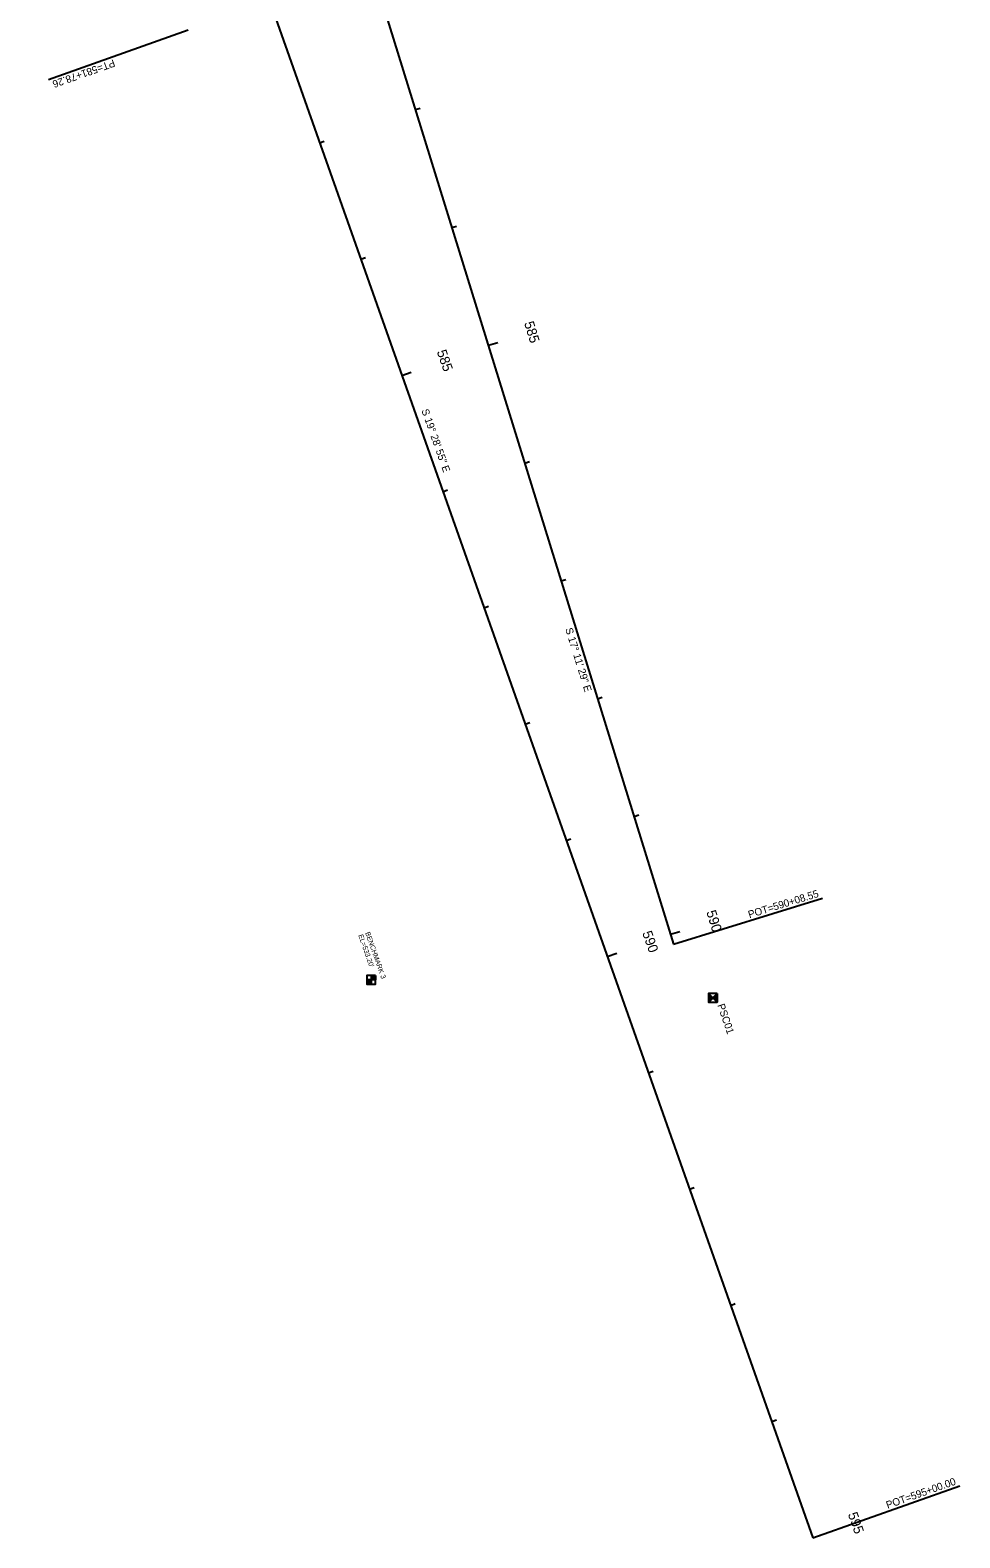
# Model space of a CAD drawing. Extents: x 2004390 to 2008791, y 1133870 to 1140084.
# Drawn here: x 2006440 to 2007194, y 1133870 to 1135092 of the extents above; entities that cross this region are included whole.
import ezdxf

# ---------------------------------------------------------------- set-up
doc = ezdxf.new("R2010")
doc.units = 0
for name, color, linetype in [('RD_HC_Cl', 7, 'Continuous'), ('RD_HC_Data', 7, 'Continuous'), ('RD_HC_Data_Tic', 7, 'Continuous'), ('RD_HC_Survey', 7, 'Continuous'), ('RD_HC_Survey_txCode', 7, 'Continuous'), ('RD_HC_TX_Sta50', 7, 'Continuous')]:
    doc.layers.add(name, color=color, linetype=linetype)

msp = doc.modelspace()

# ---------------------------------------------------------------- linework, layer by layer
at = {"layer": 'RD_HC_Cl'}
for p, q in [((2005036.1, 1139633.5), (2007075.2, 1133869.8)), ((2006488, 1135883.7), (2006962.2, 1134351.1))]:
    msp.add_line(p, q, dxfattribs=at)
at = {"layer": 'RD_HC_Data'}
for p, q in [((2006568.4, 1135092.5), (2006454.9, 1135052.3)), ((2006962.2, 1134351.1), (2007083, 1134388.5)), ((2007075.2, 1133869.8), (2007194.4, 1133912))]:
    msp.add_line(p, q, dxfattribs=at)
at = {"layer": 'RD_HC_Data_Tic'}
for p, q in [((2006752.7, 1135028), (2006756.6, 1135029.2)), ((2006675, 1135001.1), (2006678.7, 1135002.4)), ((2006782.3, 1134932.5), (2006786.1, 1134933.6)), ((2006708.3, 1134906.8), (2006712.1, 1134908.1)), ((2006811.9, 1134836.9), (2006819.5, 1134839.3)), ((2006741.7, 1134812.5), (2006749.2, 1134815.2)), ((2006841.4, 1134741.4), (2006845.2, 1134742.6)), ((2006775, 1134718.2), (2006778.8, 1134719.6)), ((2006871, 1134645.9), (2006874.8, 1134647)), ((2006808.4, 1134624), (2006812.1, 1134625.3)), ((2006900.5, 1134550.3), (2006904.3, 1134551.5)), ((2006841.7, 1134529.7), (2006845.5, 1134531)), ((2006930.1, 1134454.8), (2006933.9, 1134456)), ((2006875.1, 1134435.4), (2006878.8, 1134436.7)), ((2006959.6, 1134359.3), (2006967.3, 1134361.6)), ((2006908.4, 1134341.1), (2006916, 1134343.8)), ((2006941.8, 1134246.9), (2006945.5, 1134248.2)), ((2006975.1, 1134152.6), (2006978.9, 1134153.9)), ((2007008.5, 1134058.3), (2007012.2, 1134059.7)), ((2007041.8, 1133964), (2007045.6, 1133965.4)), ((2007075.2, 1133869.8), (2007082.7, 1133872.4))]:
    msp.add_line(p, q, dxfattribs=at)
at = {"layer": 'RD_HC_Survey'}
for p, q in [((2006720.3, 1134322.3), (2006713.3, 1134322.3)), ((2006713.3, 1134322.3), (2006713.3, 1134318.8)), ((2006713.3, 1134322.3), (2006713.3, 1134318.8)), ((2006713.4, 1134322.3), (2006713.4, 1134318.8)), ((2006713.4, 1134322.3), (2006713.4, 1134318.8)), ((2006713.5, 1134322.3), (2006713.5, 1134318.8)), ((2006713.5, 1134322.3), (2006713.5, 1134318.8)), ((2006713.6, 1134322.3), (2006713.6, 1134318.8)), ((2006713.6, 1134322.3), (2006713.6, 1134318.8)), ((2006713.7, 1134322.3), (2006713.7, 1134318.8)), ((2006713.7, 1134322.3), (2006713.7, 1134318.8)), ((2006713.8, 1134322.3), (2006713.8, 1134318.8)), ((2006713.8, 1134322.3), (2006713.8, 1134318.8)), ((2006713.9, 1134322.3), (2006713.9, 1134318.8)), ((2006713.9, 1134322.3), (2006713.9, 1134318.8)), ((2006714, 1134322.3), (2006714, 1134318.8)), ((2006714, 1134322.3), (2006714, 1134318.8)), ((2006714.1, 1134322.3), (2006714.1, 1134318.8)), ((2006714.1, 1134322.3), (2006714.1, 1134318.8)), ((2006714.2, 1134322.3), (2006714.2, 1134318.8)), ((2006714.2, 1134322.3), (2006714.2, 1134318.8)), ((2006714.3, 1134322.3), (2006714.3, 1134318.8)), ((2006714.3, 1134322.3), (2006714.3, 1134318.8)), ((2006714.4, 1134322.3), (2006714.4, 1134318.8)), ((2006714.4, 1134322.3), (2006714.4, 1134318.8)), ((2006714.5, 1134322.3), (2006714.5, 1134318.8)), ((2006714.5, 1134322.3), (2006714.5, 1134318.8)), ((2006714.6, 1134322.3), (2006714.6, 1134318.8)), ((2006714.6, 1134322.3), (2006714.6, 1134318.8)), ((2006714.7, 1134322.3), (2006714.7, 1134318.8)), ((2006714.7, 1134322.3), (2006714.7, 1134318.8)), ((2006714.8, 1134322.3), (2006714.8, 1134318.8)), ((2006714.8, 1134322.3), (2006714.8, 1134318.8)), ((2006714.9, 1134322.3), (2006714.9, 1134318.8)), ((2006714.9, 1134322.3), (2006714.9, 1134318.8)), ((2006715, 1134322.3), (2006715, 1134318.8)), ((2006715, 1134322.3), (2006715, 1134318.8)), ((2006715.1, 1134322.3), (2006715.1, 1134318.8)), ((2006715.1, 1134322.3), (2006715.1, 1134318.8)), ((2006715.2, 1134322.3), (2006715.2, 1134318.8)), ((2006715.2, 1134322.3), (2006715.2, 1134318.8)), ((2006715.3, 1134322.3), (2006715.3, 1134318.8)), ((2006715.3, 1134322.3), (2006715.3, 1134318.8)), ((2006715.4, 1134322.3), (2006715.4, 1134318.8)), ((2006715.4, 1134322.3), (2006715.4, 1134318.8)), ((2006715.5, 1134322.3), (2006715.5, 1134318.8)), ((2006715.5, 1134322.3), (2006715.5, 1134318.8)), ((2006715.6, 1134322.3), (2006715.6, 1134318.8)), ((2006715.6, 1134322.3), (2006715.6, 1134318.8)), ((2006715.7, 1134322.3), (2006715.7, 1134318.8)), ((2006715.7, 1134322.3), (2006715.7, 1134318.8)), ((2006715.8, 1134322.3), (2006715.8, 1134318.8)), ((2006715.8, 1134322.3), (2006715.8, 1134318.8)), ((2006715.9, 1134322.3), (2006715.9, 1134318.8)), ((2006715.9, 1134322.3), (2006715.9, 1134318.8)), ((2006716, 1134322.3), (2006716, 1134318.8)), ((2006716, 1134322.3), (2006716, 1134318.8)), ((2006716.1, 1134322.3), (2006716.1, 1134318.8)), ((2006716.1, 1134322.3), (2006716.1, 1134318.8)), ((2006716.2, 1134322.3), (2006716.2, 1134318.8)), ((2006716.2, 1134322.3), (2006716.2, 1134318.8)), ((2006716.3, 1134322.3), (2006716.3, 1134318.8)), ((2006716.3, 1134322.3), (2006716.3, 1134318.8)), ((2006716.4, 1134322.3), (2006716.4, 1134318.8)), ((2006716.4, 1134322.3), (2006716.4, 1134318.8)), ((2006716.5, 1134322.3), (2006716.5, 1134318.8)), ((2006716.5, 1134322.3), (2006716.5, 1134318.8)), ((2006716.6, 1134322.3), (2006716.6, 1134318.8)), ((2006716.6, 1134322.3), (2006716.6, 1134318.8)), ((2006716.7, 1134322.3), (2006716.7, 1134318.8)), ((2006716.7, 1134322.3), (2006716.7, 1134318.8)), ((2006716.8, 1134325.8), (2006716.8, 1134318.8)), ((2006716.8, 1134325.8), (2006716.8, 1134322.3)), ((2006716.8, 1134322.3), (2006716.8, 1134318.8)), ((2006716.9, 1134325.8), (2006716.9, 1134322.3)), ((2006716.9, 1134325.8), (2006716.9, 1134322.3)), ((2006717, 1134325.8), (2006717, 1134322.3)), ((2006717, 1134325.8), (2006717, 1134322.3)), ((2006717.1, 1134325.8), (2006717.1, 1134322.3)), ((2006717.1, 1134325.8), (2006717.1, 1134322.3)), ((2006717.2, 1134325.8), (2006717.2, 1134322.3)), ((2006717.2, 1134325.8), (2006717.2, 1134322.3)), ((2006717.3, 1134325.8), (2006717.3, 1134322.3)), ((2006717.3, 1134325.8), (2006717.3, 1134322.3)), ((2006717.4, 1134325.8), (2006717.4, 1134322.3)), ((2006717.4, 1134325.8), (2006717.4, 1134322.3)), ((2006717.5, 1134325.8), (2006717.5, 1134322.3)), ((2006717.5, 1134325.8), (2006717.5, 1134322.3)), ((2006717.6, 1134325.8), (2006717.6, 1134322.3)), ((2006717.6, 1134325.8), (2006717.6, 1134322.3)), ((2006717.7, 1134325.8), (2006717.7, 1134322.3)), ((2006717.7, 1134325.8), (2006717.7, 1134322.3)), ((2006717.8, 1134325.8), (2006717.8, 1134322.3)), ((2006717.8, 1134325.8), (2006717.8, 1134322.3)), ((2006717.9, 1134325.8), (2006717.9, 1134322.3)), ((2006717.9, 1134325.8), (2006717.9, 1134322.3)), ((2006718, 1134325.8), (2006718, 1134322.3)), ((2006718, 1134325.8), (2006718, 1134322.3)), ((2006718.1, 1134325.8), (2006718.1, 1134322.3)), ((2006718.1, 1134325.8), (2006718.1, 1134322.3)), ((2006718.2, 1134325.8), (2006718.2, 1134322.3)), ((2006718.2, 1134325.8), (2006718.2, 1134322.3)), ((2006718.3, 1134325.8), (2006718.3, 1134322.3)), ((2006718.3, 1134325.8), (2006718.3, 1134322.3)), ((2006718.4, 1134325.8), (2006718.4, 1134322.3)), ((2006718.4, 1134325.8), (2006718.4, 1134322.3)), ((2006718.5, 1134325.8), (2006718.5, 1134322.3)), ((2006718.5, 1134325.8), (2006718.5, 1134322.3)), ((2006718.6, 1134325.8), (2006718.6, 1134322.3)), ((2006718.6, 1134325.8), (2006718.6, 1134322.3)), ((2006718.7, 1134325.8), (2006718.7, 1134322.3)), ((2006718.7, 1134325.8), (2006718.7, 1134322.3)), ((2006718.8, 1134325.8), (2006718.8, 1134322.3)), ((2006718.8, 1134325.8), (2006718.8, 1134322.3)), ((2006718.9, 1134325.8), (2006718.9, 1134322.3)), ((2006718.9, 1134325.8), (2006718.9, 1134322.3)), ((2006719, 1134325.8), (2006719, 1134322.3)), ((2006719, 1134325.8), (2006719, 1134322.3)), ((2006719.1, 1134325.8), (2006719.1, 1134322.3)), ((2006719.1, 1134325.8), (2006719.1, 1134322.3)), ((2006719.2, 1134325.8), (2006719.2, 1134322.3)), ((2006719.2, 1134325.8), (2006719.2, 1134322.3)), ((2006719.3, 1134325.8), (2006719.3, 1134322.3)), ((2006719.3, 1134325.8), (2006719.3, 1134322.3)), ((2006719.4, 1134325.8), (2006719.4, 1134322.3)), ((2006719.4, 1134325.8), (2006719.4, 1134322.3)), ((2006719.5, 1134325.8), (2006719.5, 1134322.3)), ((2006719.5, 1134325.8), (2006719.5, 1134322.3)), ((2006719.6, 1134325.8), (2006719.6, 1134322.3)), ((2006719.6, 1134325.8), (2006719.6, 1134322.3)), ((2006719.7, 1134325.8), (2006719.7, 1134322.3)), ((2006719.7, 1134325.8), (2006719.7, 1134322.3)), ((2006719.8, 1134325.8), (2006719.8, 1134322.3)), ((2006719.8, 1134325.8), (2006719.8, 1134322.3)), ((2006719.9, 1134325.8), (2006719.9, 1134322.3)), ((2006719.9, 1134325.8), (2006719.9, 1134322.3)), ((2006720, 1134325.8), (2006720, 1134322.3)), ((2006720, 1134325.8), (2006720, 1134322.3)), ((2006720.1, 1134325.8), (2006720.1, 1134322.3)), ((2006720.1, 1134325.8), (2006720.1, 1134322.3)), ((2006720.2, 1134325.8), (2006720.2, 1134322.3)), ((2006720.2, 1134325.8), (2006720.2, 1134322.3)), ((2006720.3, 1134325.8), (2006720.3, 1134322.3)), ((2006990.5, 1134311.1), (2006997.6, 1134304.1)), ((2006997.6, 1134311.1), (2006990.5, 1134304.1)), ((2006990.5, 1134311.1), (2006990.5, 1134304.1)), ((2006990.6, 1134311), (2006990.6, 1134304.2)), ((2006990.6, 1134311), (2006990.6, 1134304.2)), ((2006990.7, 1134310.9), (2006990.7, 1134304.3)), ((2006990.7, 1134310.9), (2006990.7, 1134304.3)), ((2006990.8, 1134310.8), (2006990.8, 1134304.4)), ((2006990.8, 1134310.8), (2006990.8, 1134304.4)), ((2006990.9, 1134310.7), (2006990.9, 1134304.5)), ((2006990.9, 1134310.7), (2006990.9, 1134304.5)), ((2006991, 1134310.6), (2006991, 1134304.6)), ((2006991, 1134310.6), (2006991, 1134304.6)), ((2006991.1, 1134310.5), (2006991.1, 1134304.7)), ((2006991.1, 1134310.5), (2006991.1, 1134304.7)), ((2006991.2, 1134310.4), (2006991.2, 1134304.8)), ((2006991.2, 1134310.4), (2006991.2, 1134304.8)), ((2006991.3, 1134310.3), (2006991.3, 1134304.9)), ((2006991.3, 1134310.3), (2006991.3, 1134304.9)), ((2006991.4, 1134310.2), (2006991.4, 1134305)), ((2006991.4, 1134310.2), (2006991.4, 1134305)), ((2006991.5, 1134310.1), (2006991.5, 1134305.1)), ((2006991.5, 1134310.1), (2006991.5, 1134305.1)), ((2006991.6, 1134310), (2006991.6, 1134305.2)), ((2006991.6, 1134310), (2006991.6, 1134305.2)), ((2006991.7, 1134309.9), (2006991.7, 1134305.3)), ((2006991.7, 1134309.9), (2006991.7, 1134305.3)), ((2006991.8, 1134309.8), (2006991.8, 1134305.4)), ((2006991.8, 1134309.8), (2006991.8, 1134305.4)), ((2006991.9, 1134309.7), (2006991.9, 1134305.5)), ((2006991.9, 1134309.7), (2006991.9, 1134305.5)), ((2006992, 1134309.6), (2006992, 1134305.6)), ((2006992, 1134309.6), (2006992, 1134305.6)), ((2006992.1, 1134309.5), (2006992.1, 1134305.7)), ((2006992.1, 1134309.5), (2006992.1, 1134305.7)), ((2006992.2, 1134309.4), (2006992.2, 1134305.8)), ((2006992.2, 1134309.4), (2006992.2, 1134305.8)), ((2006992.3, 1134309.3), (2006992.3, 1134305.9)), ((2006992.3, 1134309.3), (2006992.3, 1134305.9)), ((2006992.4, 1134309.2), (2006992.4, 1134306)), ((2006992.4, 1134309.2), (2006992.4, 1134306)), ((2006992.5, 1134309.1), (2006992.5, 1134306.1)), ((2006992.5, 1134309.1), (2006992.5, 1134306.1)), ((2006992.6, 1134309), (2006992.6, 1134306.2)), ((2006992.6, 1134309), (2006992.6, 1134306.2)), ((2006992.7, 1134308.9), (2006992.7, 1134306.3)), ((2006992.7, 1134308.9), (2006992.7, 1134306.3)), ((2006992.8, 1134308.8), (2006992.8, 1134306.4)), ((2006992.8, 1134308.8), (2006992.8, 1134306.4)), ((2006992.9, 1134308.7), (2006992.9, 1134306.5)), ((2006992.9, 1134308.7), (2006992.9, 1134306.5)), ((2006993, 1134308.6), (2006993, 1134306.6)), ((2006993, 1134308.6), (2006993, 1134306.6)), ((2006993.1, 1134308.5), (2006993.1, 1134306.7)), ((2006993.1, 1134308.5), (2006993.1, 1134306.7)), ((2006993.2, 1134308.4), (2006993.2, 1134306.8)), ((2006993.2, 1134308.4), (2006993.2, 1134306.8)), ((2006993.3, 1134308.3), (2006993.3, 1134306.9)), ((2006993.3, 1134308.3), (2006993.3, 1134306.9)), ((2006993.4, 1134308.2), (2006993.4, 1134307)), ((2006993.4, 1134308.2), (2006993.4, 1134307)), ((2006993.5, 1134308.1), (2006993.5, 1134307.1)), ((2006993.5, 1134308.1), (2006993.5, 1134307.1)), ((2006993.6, 1134308), (2006993.6, 1134307.2)), ((2006993.6, 1134308), (2006993.6, 1134307.2)), ((2006993.7, 1134307.9), (2006993.7, 1134307.3)), ((2006993.7, 1134307.9), (2006993.7, 1134307.3)), ((2006993.8, 1134307.8), (2006993.8, 1134307.4)), ((2006993.8, 1134307.8), (2006993.8, 1134307.4)), ((2006993.9, 1134307.7), (2006993.9, 1134307.5)), ((2006993.9, 1134307.7), (2006993.9, 1134307.5)), ((2006994, 1134307.6), (2006994, 1134307.6)), ((2006994.1, 1134307.7), (2006994.1, 1134307.5)), ((2006994.1, 1134307.6), (2006994.1, 1134307.6)), ((2006994.2, 1134307.8), (2006994.2, 1134307.4)), ((2006994.2, 1134307.7), (2006994.2, 1134307.5)), ((2006994.3, 1134307.9), (2006994.3, 1134307.3)), ((2006994.3, 1134307.8), (2006994.3, 1134307.4)), ((2006994.4, 1134308), (2006994.4, 1134307.2)), ((2006994.4, 1134307.9), (2006994.4, 1134307.3)), ((2006994.5, 1134308.1), (2006994.5, 1134307.1)), ((2006994.5, 1134308), (2006994.5, 1134307.2)), ((2006994.6, 1134308.2), (2006994.6, 1134307)), ((2006994.6, 1134308.1), (2006994.6, 1134307.1)), ((2006994.7, 1134308.3), (2006994.7, 1134306.9)), ((2006994.7, 1134308.2), (2006994.7, 1134307)), ((2006994.8, 1134308.4), (2006994.8, 1134306.8)), ((2006994.8, 1134308.3), (2006994.8, 1134306.9)), ((2006994.9, 1134308.5), (2006994.9, 1134306.7)), ((2006994.9, 1134308.4), (2006994.9, 1134306.8)), ((2006995, 1134308.6), (2006995, 1134306.6)), ((2006995, 1134308.5), (2006995, 1134306.7)), ((2006995.1, 1134308.7), (2006995.1, 1134306.5)), ((2006995.1, 1134308.6), (2006995.1, 1134306.6)), ((2006995.2, 1134308.8), (2006995.2, 1134306.4)), ((2006995.2, 1134308.7), (2006995.2, 1134306.5)), ((2006995.3, 1134308.9), (2006995.3, 1134306.3)), ((2006995.3, 1134308.8), (2006995.3, 1134306.4)), ((2006995.4, 1134309), (2006995.4, 1134306.2)), ((2006995.4, 1134308.9), (2006995.4, 1134306.3)), ((2006995.5, 1134309.1), (2006995.5, 1134306.1)), ((2006995.5, 1134309), (2006995.5, 1134306.2)), ((2006995.6, 1134309.2), (2006995.6, 1134306)), ((2006995.6, 1134309.1), (2006995.6, 1134306.1)), ((2006995.7, 1134309.3), (2006995.7, 1134305.9)), ((2006995.7, 1134309.2), (2006995.7, 1134306)), ((2006995.8, 1134309.4), (2006995.8, 1134305.8)), ((2006995.8, 1134309.3), (2006995.8, 1134305.9)), ((2006995.9, 1134309.5), (2006995.9, 1134305.7)), ((2006995.9, 1134309.4), (2006995.9, 1134305.8)), ((2006996, 1134309.6), (2006996, 1134305.6)), ((2006996, 1134309.5), (2006996, 1134305.7)), ((2006996.1, 1134309.7), (2006996.1, 1134305.5)), ((2006996.1, 1134309.6), (2006996.1, 1134305.6)), ((2006996.2, 1134309.8), (2006996.2, 1134305.4)), ((2006996.2, 1134309.7), (2006996.2, 1134305.5)), ((2006996.3, 1134309.9), (2006996.3, 1134305.3)), ((2006996.3, 1134309.8), (2006996.3, 1134305.4)), ((2006996.4, 1134310), (2006996.4, 1134305.2)), ((2006996.4, 1134309.9), (2006996.4, 1134305.3)), ((2006996.5, 1134310.1), (2006996.5, 1134305.1)), ((2006996.5, 1134310), (2006996.5, 1134305.2)), ((2006996.6, 1134310.2), (2006996.6, 1134305)), ((2006996.6, 1134310.1), (2006996.6, 1134305.1)), ((2006996.7, 1134310.3), (2006996.7, 1134304.9)), ((2006996.7, 1134310.2), (2006996.7, 1134305)), ((2006996.8, 1134310.4), (2006996.8, 1134304.8)), ((2006996.8, 1134310.3), (2006996.8, 1134304.9)), ((2006996.9, 1134310.5), (2006996.9, 1134304.7)), ((2006996.9, 1134310.4), (2006996.9, 1134304.8)), ((2006997, 1134310.6), (2006997, 1134304.6)), ((2006997, 1134310.5), (2006997, 1134304.7)), ((2006997.1, 1134310.7), (2006997.1, 1134304.5)), ((2006997.1, 1134310.6), (2006997.1, 1134304.6)), ((2006997.2, 1134310.8), (2006997.2, 1134304.4)), ((2006997.2, 1134310.7), (2006997.2, 1134304.5)), ((2006997.3, 1134310.9), (2006997.3, 1134304.3)), ((2006997.3, 1134310.8), (2006997.3, 1134304.4)), ((2006997.4, 1134311), (2006997.4, 1134304.2)), ((2006997.4, 1134310.9), (2006997.4, 1134304.3)), ((2006997.5, 1134311.1), (2006997.5, 1134304.1)), ((2006997.5, 1134311), (2006997.5, 1134304.2))]:
    msp.add_line(p, q, dxfattribs=at)
for points in [[(2006720.3, 1134325.8), (2006713.3, 1134325.8), (2006713.3, 1134318.8), (2006720.3, 1134318.8)], [(2006997.6, 1134311.1), (2006990.5, 1134311.1), (2006990.5, 1134304.1), (2006997.6, 1134304.1)]]:
    msp.add_lwpolyline(points, close=True, dxfattribs=at)

# ---------------------------------------------------------------- texts
at = {"layer": 'RD_HC_Data'}
for s, rotation, p in [('PT=581+78.26', 199.482, (2006507.7, 1135068.9)), ('S 19%%d 28\' 55" E', 289.482, (2006757.5, 1134784.1)), ('S 17%%d 11\' 29" E', 287.1914, (2006874.2, 1134606.8)), ('POT=590+08.55', 17.1914, (2007023.7, 1134372.2)), ('POT=595+00.00', 19.482, (2007135.8, 1133893.3))]:
    msp.add_text(s, height=6, rotation=rotation, dxfattribs=at).set_placement(p)
at = {"layer": 'RD_HC_Survey_txCode'}
for s, height, rotation, p in [("EL=533.20'", 4, 289.4494, (2006706.3, 1134358.4)), ('BENCHMARK 3', 4, 289.4494, (2006711.9, 1134360.4)), ('PSC01', 6, 288.8025, (2006997.6, 1134301.8))]:
    msp.add_text(s, height=height, rotation=rotation, dxfattribs=at).set_placement(p)
at = {"layer": 'RD_HC_TX_Sta50'}
for s, rotation, p in [('585', 287.1914, (2006840.8, 1134855)), ('585', 289.482, (2006769.9, 1134831.7)), ('590', 287.1914, (2006988.6, 1134377.4)), ('590', 289.482, (2006936.6, 1134360.4)), ('595', 289.482, (2007103.4, 1133889))]:
    msp.add_text(s, height=8, rotation=rotation, dxfattribs=at).set_placement(p)

doc.saveas('drawing.dxf')
